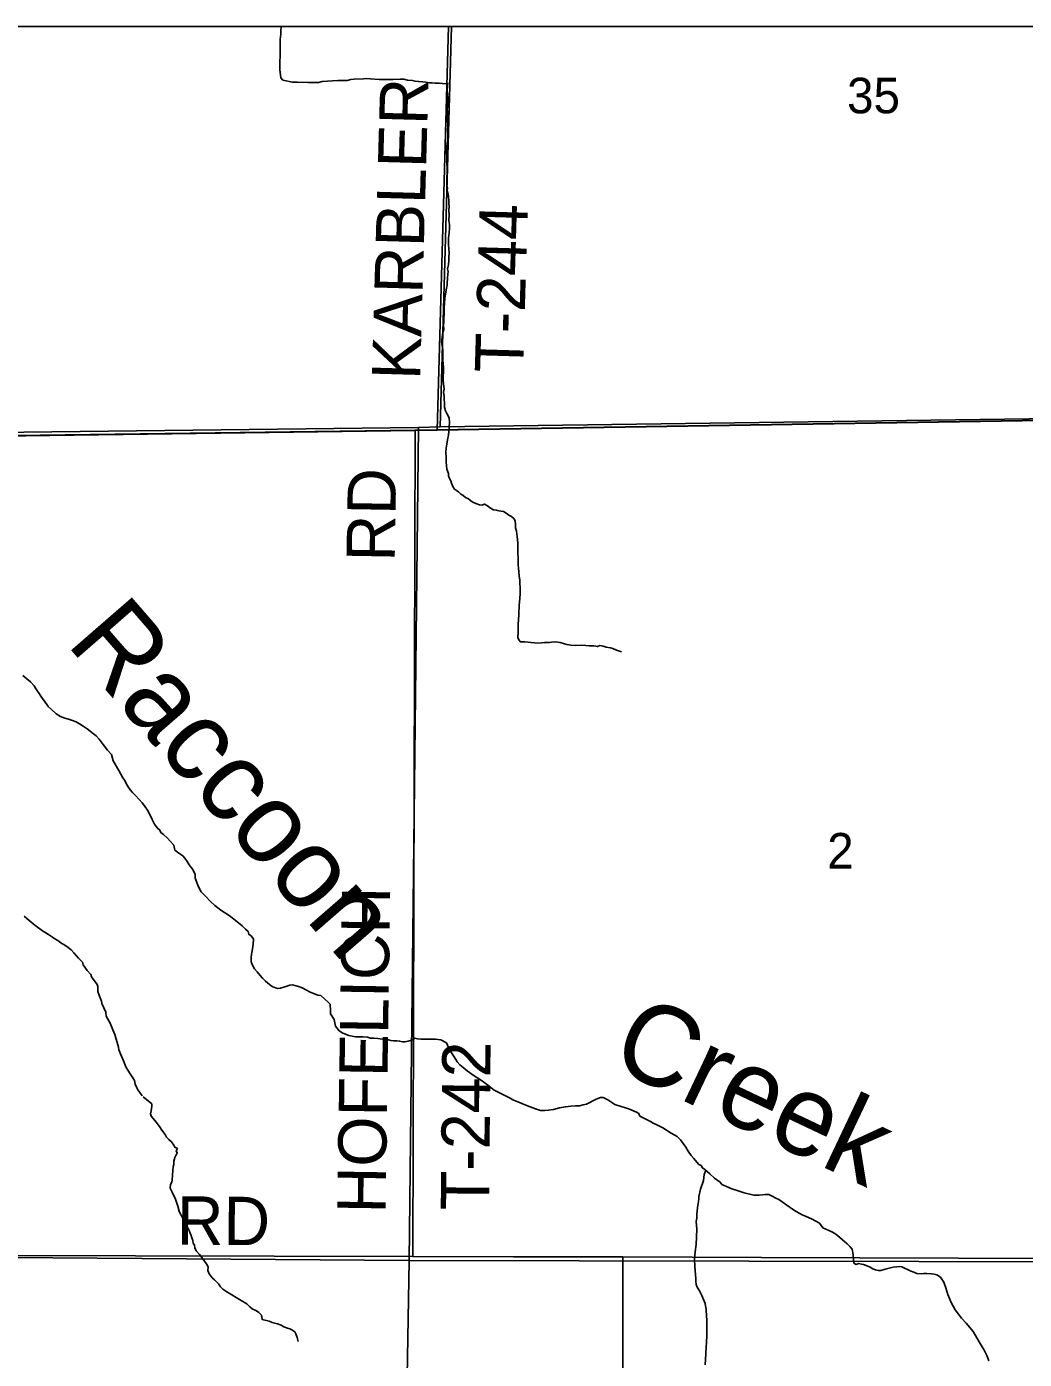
# Model space of a CAD drawing. Extents: x 0 to 34, y 0 to 22.
# Drawn here: x 6.074 to 7.249, y 19.332 to 20.9 of the extents above; entities that cross this region are included whole.
import ezdxf

# ---------------------------------------------------------------- set-up
doc = ezdxf.new("R2010")
doc.units = 0
for name, color, linetype in [('Default', 7, 'Continuous'), ('GM_X_County_Road', 7, 'Continuous'), ('GM_X_Minor_River', 7, 'Continuous'), ('GM_X_Minor_River_Text', 7, 'Continuous'), ('GM_X_Section', 7, 'Continuous'), ('GM_X_Section_Text', 7, 'Continuous'), ('GM_X_Township', 7, 'Continuous'), ('GM_X_Township_Road', 7, 'Continuous'), ('GM_X_Township_Road_Text', 7, 'Continuous'), ('SH_Cut_Line', 7, 'Continuous')]:
    doc.layers.add(name, color=color, linetype=linetype)

msp = doc.modelspace()

# ---------------------------------------------------------------- linework, layer by layer
at = {"layer": 'Default'}
for points in [[(6.5742, 20.9), (5.5805, 20.9), (5.573, 20.4171), (6.5354, 20.4284), (6.5611, 20.4294)], [(7.573, 20.9), (6.5742, 20.9), (6.5611, 20.4294), (7.5428, 20.4426), (7.5641, 20.4428)]]:
    msp.add_lwpolyline(points, close=True, dxfattribs=at)
at = {"layer": 'GM_X_County_Road'}
for points in [[(6.5577, 20.4253), (7.5411, 20.4409), (8.5562, 20.4539)], [(5.7863, 20.4148), (6.5318, 20.4249), (6.5577, 20.4253)]]:
    msp.add_lwpolyline(points, dxfattribs=at)
at = {"layer": 'GM_X_Minor_River'}
for points in [[(6.3739, 20.9), (6.3734, 20.8946), (6.3734, 20.8912), (6.3727, 20.8848), (6.3728, 20.8658), (6.3724, 20.8585), (6.3725, 20.8494), (6.3732, 20.843), (6.3736, 20.8396), (6.3759, 20.8369), (6.3873, 20.8347), (6.393, 20.8347), (6.4052, 20.8344), (6.4177, 20.8344), (6.4223, 20.8356), (6.4408, 20.8368), (6.4462, 20.8365), (6.4515, 20.8365), (6.456, 20.8377), (6.4598, 20.8381), (6.4708, 20.8385), (6.4742, 20.8389), (6.4788, 20.8385), (6.4894, 20.8378), (6.5058, 20.8379), (6.5141, 20.8383), (6.5183, 20.838), (6.5225, 20.8372), (6.5285, 20.8365), (6.5316, 20.8357), (6.5354, 20.8354), (6.5407, 20.835), (6.5441, 20.8347), (6.5479, 20.8339), (6.5517, 20.8339)], [(6.5517, 20.8339), (6.5551, 20.8336), (6.5597, 20.8336), (6.5639, 20.8332), (6.5697, 20.8328)], [(6.5663, 20.4522), (6.566, 20.4572), (6.5657, 20.4617), (6.5657, 20.4651), (6.565, 20.4701), (6.5658, 20.4735), (6.5647, 20.4837), (6.5648, 20.4985), (6.5645, 20.5042), (6.5641, 20.5073), (6.5642, 20.5198), (6.5635, 20.5251), (6.5628, 20.5289), (6.5632, 20.5343), (6.564, 20.5403), (6.5652, 20.5437), (6.5649, 20.5494), (6.5653, 20.5521), (6.5653, 20.5574), (6.5657, 20.5608), (6.5658, 20.5692), (6.5667, 20.5805), (6.5679, 20.5881), (6.5686, 20.5923), (6.5691, 20.5953), (6.5691, 20.5984), (6.5695, 20.6041), (6.5699, 20.609), (6.5703, 20.612), (6.5696, 20.6151), (6.5708, 20.6196), (6.5712, 20.6249), (6.5712, 20.6299), (6.5716, 20.6329), (6.5713, 20.639), (6.571, 20.6428), (6.571, 20.6458), (6.571, 20.6511), (6.5715, 20.6576), (6.5719, 20.6629), (6.5719, 20.6674), (6.5712, 20.672), (6.5716, 20.6788), (6.5713, 20.6838), (6.5717, 20.6887), (6.5714, 20.6914), (6.5714, 20.6952), (6.5707, 20.7001), (6.5703, 20.7031), (6.5692, 20.707), (6.5696, 20.71), (6.5689, 20.7127), (6.5689, 20.7183), (6.5691, 20.7328), (6.5687, 20.74), (6.5688, 20.7476), (6.5685, 20.7521), (6.5685, 20.7563), (6.5701, 20.7685), (6.5702, 20.7742), (6.5698, 20.7772), (6.5699, 20.7844), (6.5695, 20.7901), (6.5696, 20.7939), (6.57, 20.7977), (6.5693, 20.8026), (6.5697, 20.8057), (6.5701, 20.8095), (6.5701, 20.8163), (6.5698, 20.8197), (6.5694, 20.8239), (6.5695, 20.8304), (6.5699, 20.8338)], [(6.7744, 20.1645), (6.771, 20.1657), (6.7684, 20.1664), (6.7642, 20.1684), (6.7616, 20.1692), (6.7563, 20.17), (6.7529, 20.1711), (6.7491, 20.1719), (6.746, 20.1708), (6.7422, 20.1716), (6.7362, 20.1717), (6.7324, 20.1721), (6.7278, 20.1725), (6.7202, 20.1722), (6.7149, 20.1726), (6.71, 20.1734), (6.7074, 20.1738), (6.7024, 20.1754), (6.6968, 20.1762), (6.6922, 20.1758), (6.6896, 20.1755), (6.6839, 20.1755), (6.6801, 20.1752), (6.6755, 20.1748), (6.6721, 20.1753), (6.6676, 20.1757), (6.6645, 20.1761), (6.6607, 20.1765), (6.6581, 20.1765), (6.6554, 20.1762), (6.6536, 20.1788), (6.6524, 20.1815), (6.6529, 20.1883), (6.6529, 20.1971), (6.6538, 20.2077), (6.6538, 20.213), (6.6542, 20.216), (6.6539, 20.2195), (6.6547, 20.227), (6.6551, 20.2335), (6.6552, 20.2369), (6.6552, 20.2407), (6.6549, 20.2445), (6.6549, 20.2494), (6.6542, 20.2536), (6.6535, 20.2589), (6.6531, 20.2627), (6.6528, 20.2673), (6.6529, 20.2764), (6.6525, 20.2795), (6.6526, 20.2927), (6.6515, 20.3004), (6.6508, 20.3064), (6.6497, 20.3106), (6.6498, 20.3148), (6.6494, 20.3182), (6.6483, 20.3209), (6.6449, 20.3236), (6.6419, 20.3255), (6.6389, 20.3278), (6.6355, 20.3297), (6.6302, 20.3305), (6.6271, 20.3313), (6.6237, 20.3317), (6.6203, 20.3337), (6.6169, 20.3363), (6.6132, 20.3383), (6.6101, 20.3372), (6.6075, 20.3376), (6.6029, 20.3391), (6.6003, 20.3403), (6.5977, 20.3418), (6.5943, 20.3445), (6.5909, 20.3461), (6.5878, 20.3488), (6.5852, 20.3499), (6.5826, 20.3526), (6.578, 20.3561), (6.5758, 20.3591), (6.5743, 20.3629), (6.5736, 20.3656), (6.5721, 20.3686), (6.571, 20.3717), (6.571, 20.3743), (6.5688, 20.3793), (6.5684, 20.3839), (6.5681, 20.3877), (6.5681, 20.393), (6.5678, 20.3994), (6.5682, 20.404), (6.5686, 20.4066), (6.5698, 20.4138), (6.571, 20.4195), (6.5714, 20.4237), (6.5718, 20.429), (6.5719, 20.4347), (6.5715, 20.4396), (6.5704, 20.4423), (6.5689, 20.445), (6.5674, 20.448), (6.5663, 20.4522)], [(6.0701, 20.1369), (6.0747, 20.1327), (6.0789, 20.1293), (6.0831, 20.1244), (6.085, 20.1217), (6.0873, 20.1183), (6.0892, 20.1157), (6.0911, 20.1126), (6.098, 20.1028), (6.0999, 20.1001), (6.1037, 20.0967), (6.109, 20.0915), (6.1144, 20.0884), (6.1193, 20.0866), (6.1235, 20.0854), (6.1284, 20.0839), (6.1326, 20.0824), (6.1364, 20.0798), (6.141, 20.0772), (6.1456, 20.0742), (6.1532, 20.0681), (6.1562, 20.0658), (6.1597, 20.0617), (6.1643, 20.0556), (6.1696, 20.0488), (6.1742, 20.0439), (6.1761, 20.0363), (6.183, 20.0249), (6.1876, 20.0162), (6.1899, 20.0132), (6.1914, 20.0098), (6.1937, 20.0056), (6.1964, 20.0022), (6.1991, 19.9992), (6.2025, 19.9954), (6.2067, 19.9909), (6.2102, 19.9871), (6.2132, 19.9833), (6.2174, 19.9773), (6.222, 19.9674), (6.2247, 19.9617), (6.2281, 19.9576), (6.2312, 19.9549), (6.2323, 19.9519), (6.2354, 19.9496), (6.24, 19.9455), (6.2434, 19.942), (6.2476, 19.9371), (6.2488, 19.9314), (6.2533, 19.9277), (6.2583, 19.9246), (6.2606, 19.922), (6.2633, 19.9178), (6.2656, 19.914), (6.2698, 19.9087), (6.2728, 19.9027), (6.2729, 19.8989), (6.274, 19.8951), (6.2759, 19.8902), (6.2775, 19.8864), (6.2798, 19.8822), (6.2851, 19.8769), (6.2905, 19.8712), (6.2958, 19.8663), (6.303, 19.8607), (6.3126, 19.8543), (6.3217, 19.8475), (6.3282, 19.8422), (6.332, 19.8384), (6.335, 19.8357), (6.3358, 19.8323), (6.3392, 19.8301), (6.3412, 19.8267), (6.3408, 19.8206), (6.3401, 19.8153), (6.3393, 19.8111), (6.339, 19.8084), (6.3386, 19.805), (6.3386, 19.8004), (6.3394, 19.7974), (6.3425, 19.7917), (6.3455, 19.7883), (6.3494, 19.7838), (6.352, 19.7807), (6.3555, 19.7773), (6.36, 19.7732), (6.3635, 19.7709)], [(6.0715, 19.8537), (6.0775, 19.8486), (6.0842, 19.8432), (6.0931, 19.8365), (6.1002, 19.8322), (6.1047, 19.8291), (6.1077, 19.8271), (6.111, 19.8252), (6.1148, 19.8224), (6.1192, 19.8197), (6.1233, 19.8166), (6.1267, 19.8139), (6.13, 19.8104), (6.1356, 19.8042), (6.14, 19.7996), (6.1411, 19.7965), (6.1455, 19.7896), (6.1499, 19.7849), (6.1506, 19.7823), (6.1573, 19.7734), (6.158, 19.7708), (6.1583, 19.7681), (6.1582, 19.7651), (6.16, 19.7597), (6.1625, 19.7536), (6.1629, 19.7509), (6.1676, 19.7406), (6.1679, 19.736), (6.1726, 19.7276), (6.1759, 19.7199), (6.178, 19.7146), (6.1826, 19.6997), (6.1829, 19.6963), (6.1862, 19.689), (6.1883, 19.6833), (6.1912, 19.6764), (6.1934, 19.6726), (6.1964, 19.6683), (6.1993, 19.6633), (6.2015, 19.6603), (6.2022, 19.6561)], [(6.3635, 19.7709), (6.3673, 19.7694), (6.3699, 19.7687), (6.373, 19.7691), (6.3783, 19.7706), (6.384, 19.7725), (6.3874, 19.7729), (6.39, 19.7722), (6.3942, 19.7711), (6.3988, 19.7692), (6.4037, 19.7666), (6.4079, 19.7643), (6.417, 19.7609), (6.4205, 19.7602), (6.4254, 19.756), (6.4292, 19.7526), (6.4315, 19.75), (6.4319, 19.7424), (6.432, 19.7386), (6.4362, 19.7321), (6.4377, 19.7242), (6.4423, 19.7189), (6.4465, 19.7162), (6.4537, 19.7132), (6.4613, 19.7118), (6.4704, 19.7118), (6.4754, 19.7114), (6.4792, 19.7103), (6.483, 19.71), (6.4875, 19.7096), (6.4932, 19.7089), (6.4966, 19.7085), (6.5004, 19.7081), (6.5031, 19.7074), (6.5061, 19.707), (6.5099, 19.707), (6.5133, 19.7067), (6.5168, 19.7059), (6.5194, 19.706), (6.5232, 19.7067), (6.5262, 19.7075), (6.5289, 19.7083)], [(6.5284, 19.7081), (6.5312, 19.7102), (6.5342, 19.7094), (6.5384, 19.7091), (6.5486, 19.7091), (6.5555, 19.7088), (6.5619, 19.7081), (6.5684, 19.7047), (6.5715, 19.6971), (6.5768, 19.6895), (6.5795, 19.685), (6.581, 19.6823), (6.5841, 19.6789), (6.5883, 19.6755), (6.5929, 19.6717), (6.5997, 19.6665), (6.6054, 19.6631), (6.6108, 19.6597), (6.6172, 19.6548), (6.6245, 19.6491), (6.6435, 19.6397), (6.6466, 19.6378), (6.6523, 19.6352), (6.6572, 19.6333), (6.6618, 19.6314), (6.6671, 19.6292), (6.6732, 19.6269), (6.6793, 19.6251), (6.6842, 19.6251), (6.6887, 19.6255), (6.6944, 19.6263), (6.7016, 19.6282), (6.7085, 19.6294), (6.7149, 19.6302), (6.7202, 19.6306), (6.7252, 19.6306), (6.7293, 19.6317), (6.7331, 19.6325), (6.7445, 19.6383), (6.7498, 19.6402), (6.7528, 19.6402), (6.7585, 19.6376), (6.7665, 19.6323), (6.7753, 19.6293), (6.7779, 19.6286), (6.784, 19.6267), (6.792, 19.6233), (6.7947, 19.6214), (6.7962, 19.6184), (6.8038, 19.6146), (6.8084, 19.612), (6.8118, 19.6101), (6.816, 19.6082), (6.8229, 19.6045), (6.8328, 19.5984), (6.84, 19.5943), (6.8438, 19.5905), (6.8472, 19.5863), (6.8503, 19.5818), (6.853, 19.5773), (6.8564, 19.5723), (6.8595, 19.5686), (6.8629, 19.5644), (6.8656, 19.5617), (6.8682, 19.5602), (6.8698, 19.5576), (6.8724, 19.5557), (6.8782, 19.5504), (6.8839, 19.5455), (6.8904, 19.5406), (6.8927, 19.5379), (6.898, 19.5357), (6.9041, 19.5331), (6.9105, 19.5308), (6.9189, 19.5282), (6.9303, 19.5256), (6.9364, 19.5256), (6.9402, 19.526), (6.9436, 19.5264), (6.9478, 19.5261), (6.9519, 19.5242), (6.9561, 19.5219), (6.9595, 19.5204), (6.9634, 19.5178), (6.9691, 19.5136), (6.9755, 19.5091), (6.9801, 19.5061), (6.9843, 19.5038), (6.987, 19.5023), (6.9919, 19.5004), (6.998, 19.4978), (7.0041, 19.4944), (7.0075, 19.4925), (7.0113, 19.4872), (7.022, 19.4823), (7.0254, 19.4805), (7.0288, 19.4782), (7.0346, 19.4729), (7.0399, 19.4684), (7.0433, 19.465), (7.046, 19.4619)], [(6.2022, 19.6561), (6.204, 19.6519), (6.2054, 19.6492), (6.2076, 19.6461), (6.2102, 19.6423)], [(6.3941, 19.3534), (6.3926, 19.358), (6.3911, 19.3622), (6.39, 19.3649), (6.3866, 19.3672), (6.384, 19.3683), (6.3813, 19.3691), (6.3772, 19.3707), (6.3738, 19.3726), (6.3696, 19.3742), (6.3632, 19.3757), (6.3598, 19.3773), (6.3514, 19.3793), (6.3507, 19.3842), (6.3477, 19.3873), (6.3447, 19.3896), (6.3398, 19.3919), (6.3371, 19.3942), (6.3334, 19.3976), (6.327, 19.4015), (6.31, 19.4119), (6.3051, 19.415), (6.3025, 19.4177), (6.3002, 19.4211), (6.2953, 19.4257), (6.2927, 19.4284), (6.2893, 19.433), (6.2878, 19.4368), (6.2882, 19.4413), (6.2864, 19.444), (6.283, 19.449), (6.2777, 19.4555), (6.274, 19.4601), (6.2725, 19.4635), (6.2718, 19.4665), (6.2703, 19.4692), (6.2699, 19.4722), (6.2688, 19.4753), (6.2681, 19.4779), (6.267, 19.4806), (6.2655, 19.484), (6.2625, 19.4901), (6.2591, 19.4962), (6.2573, 19.5001), (6.2554, 19.5031), (6.2539, 19.5065), (6.2524, 19.5126), (6.2495, 19.5206), (6.2457, 19.529), (6.2431, 19.5336), (6.2435, 19.5382), (6.2451, 19.5408), (6.2455, 19.5434), (6.2459, 19.5491), (6.2463, 19.5544), (6.2468, 19.559), (6.2475, 19.5617), (6.2476, 19.5654), (6.2487, 19.5696), (6.2499, 19.5723), (6.2514, 19.5749), (6.2503, 19.5776), (6.2519, 19.5802), (6.2488, 19.5818), (6.2477, 19.5844), (6.2447, 19.5883), (6.2417, 19.5909), (6.2391, 19.5936), (6.2376, 19.5967), (6.2335, 19.602), (6.2308, 19.6062), (6.2267, 19.6112), (6.2233, 19.6158), (6.2211, 19.6185), (6.2203, 19.6211), (6.2211, 19.6245), (6.2215, 19.6276), (6.2219, 19.6302), (6.2216, 19.6329), (6.2115, 19.6413)], [(6.8736, 19.5546), (6.8717, 19.5496), (6.871, 19.5428), (6.8676, 19.5325), (6.8654, 19.5238), (6.8654, 19.5211), (6.865, 19.5181), (6.8639, 19.5108), (6.8632, 19.5029), (6.8629, 19.4983), (6.8625, 19.4945), (6.8629, 19.4854), (6.8623, 19.4675), (6.8612, 19.4588), (6.8604, 19.4504), (6.8609, 19.4413), (6.8621, 19.4276), (6.8621, 19.4242), (6.8625, 19.4204), (6.8636, 19.4174), (6.8663, 19.4128), (6.869, 19.4075), (6.8729, 19.3981), (6.8732, 19.3954), (6.874, 19.3912), (6.8744, 19.3825), (6.8748, 19.3795), (6.8749, 19.37), (6.8749, 19.3605), (6.8746, 19.3521), (6.8742, 19.3472), (6.8735, 19.3388), (6.8728, 19.3259)], [(7.046, 19.4619), (7.0472, 19.4555), (7.0476, 19.4487), (7.048, 19.4456), (7.0507, 19.4441), (7.0533, 19.4449), (7.0567, 19.4445), (7.0594, 19.4438), (7.0624, 19.4427), (7.067, 19.4408), (7.0704, 19.4389), (7.0735, 19.4378), (7.0765, 19.437), (7.0795, 19.437), (7.0848, 19.4386), (7.0943, 19.4409), (7.0985, 19.4413), (7.1015, 19.4417), (7.1042, 19.441), (7.1076, 19.4398), (7.111, 19.4379), (7.1141, 19.4364), (7.1186, 19.4349), (7.1221, 19.4334), (7.127, 19.4331), (7.1304, 19.4335), (7.1338, 19.4335), (7.1392, 19.4328), (7.1422, 19.4324), (7.1456, 19.4317), (7.1498, 19.429), (7.1536, 19.4233), (7.1563, 19.4165), (7.1586, 19.4085), (7.1625, 19.3991), (7.1671, 19.3907), (7.1709, 19.3854), (7.1747, 19.3809), (7.1801, 19.3748), (7.1881, 19.365), (7.1954, 19.3529), (7.2011, 19.343), (7.2045, 19.337), (7.2069, 19.3305)]]:
    msp.add_lwpolyline(points, dxfattribs=at)
at = {"layer": 'GM_X_Section'}
for points in [[(7.5428, 20.4426), (7.5241, 19.4466), (6.5246, 19.4487), (6.5354, 20.4284), (6.5611, 20.4294)], [(6.5354, 20.4284), (6.5246, 19.4487), (5.5276, 19.4562), (5.5347, 20.4166), (5.573, 20.4171)], [(6.5246, 19.4487), (6.5078, 18.4687), (5.5161, 18.4568), (5.5276, 19.4562)], [(6.5246, 19.4487), (7.5241, 19.4466), (7.5189, 18.4589), (6.5078, 18.4687)]]:
    msp.add_lwpolyline(points, close=True, dxfattribs=at)
at = {"layer": 'GM_X_Township'}
msp.add_lwpolyline([(4.5784, 20.3968), (5.284, 20.4086), (5.325, 20.4092), (6.5316, 20.4254), (6.5575, 20.4259), (7.5409, 20.4415), (8.556, 20.4544), (8.5437, 19.4556), (8.5436, 19.4447), (8.5388, 18.7451), (8.5216, 17.7888), (8.5215, 17.7806), (8.5214, 17.7731), (8.5094, 16.832), (8.5093, 16.83), (8.4947, 15.4259), (8.4895, 15.0042)], dxfattribs=at)
at = {"layer": 'GM_X_Township_Road'}
for p, q in [((6.5577, 20.4253), (6.5707, 20.9)), ((6.5287, 19.4533), (6.5318, 20.4249)), ((5.864, 19.4548), (6.5287, 19.4533))]:
    msp.add_line(p, q, dxfattribs=at)
for points in [[(4.5784, 20.3968), (5.284, 20.4086), (5.325, 20.4092), (6.5316, 20.4254), (6.5575, 20.4259), (7.5409, 20.4415), (8.556, 20.4544), (8.5676, 20.9), (2.6262, 20.9)], [(6.5287, 19.4533), (6.6475, 19.4531), (6.7761, 19.4529)], [(6.7743, 18.8809), (6.7759, 19.0338), (6.7759, 19.3078), (6.7761, 19.4529)], [(6.7761, 19.4529), (6.939, 19.4523), (7.4021, 19.4507), (7.5295, 19.4511)]]:
    msp.add_lwpolyline(points, dxfattribs=at)
at = {"layer": 'SH_Cut_Line'}
msp.add_lwpolyline([(8.9, 14.4215), (8.9, 20.9), (2.1, 20.9)], dxfattribs=at)

# ---------------------------------------------------------------- texts
at = {"layer": 'GM_X_Minor_River_Text'}
for s, rotation, p in [('Raccoon', 310.9846, (6.1199, 20.1743)), ('Creek', 334.6353, (6.7579, 19.6788))]:
    msp.add_text(s, height=0.09475, rotation=rotation, dxfattribs=at).set_placement(p)
at = {"layer": 'GM_X_Section_Text'}
for s, height, p in [('35', 0.04186, (7.0399, 20.798)), ('2', 0.0419, (7.0165, 19.9096))]:
    msp.add_text(s, height=height, rotation=0, dxfattribs=at).set_placement(p)
at = {"layer": 'GM_X_Township_Road_Text'}
for s, rotation, p in [('KARBLER', 88.3806, (6.5374, 20.484)), ('T-244', 88.3152, (6.6585, 20.4922)), ('RD', 89.0128, (6.5075, 20.2704)), ('HOFELICH', 89.1656, (6.4967, 19.5037)), ('T-242', 89.4386, (6.6185, 19.5074)), ('RD', 359.5063, (6.2509, 19.4674))]:
    msp.add_text(s, height=0.05682, rotation=rotation, dxfattribs=at).set_placement(p)

doc.saveas('drawing.dxf')
